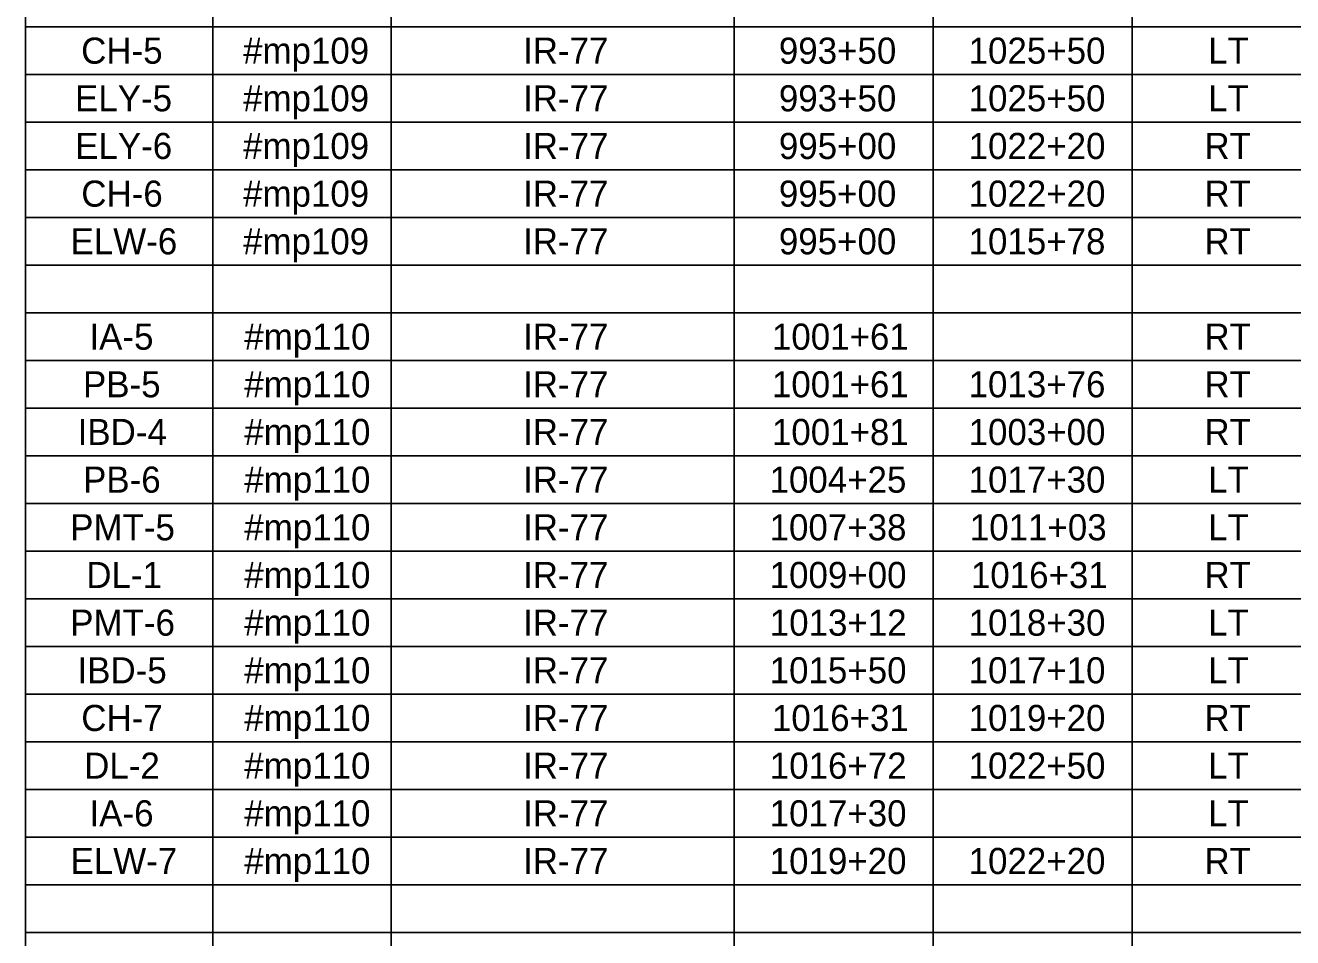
# Model space of a CAD drawing. Extents: x 91011267 to 91022583, y 37007614 to 37014266.
# Drawn here: x 91011277.4 to 91011642.6, y 37010698.6 to 37010961.6 of the extents above; entities that cross this region are included whole.
import ezdxf

# ---------------------------------------------------------------- set-up
doc = ezdxf.new("R2010")
doc.units = 0
doc.layers.add('SC_Scratch2', color=7, linetype='Continuous')
doc.layers.add('SH_Data', color=7, linetype='Continuous')

msp = doc.modelspace()

# ---------------------------------------------------------------- linework, layer by layer
at = {"layer": 'SC_Scratch2'}
msp.add_lwpolyline([(91011277.35, 37011225.45), (91012802.35, 37011225.45), (91012802.35, 37010175.45), (91011277.35, 37010175.45)], close=True, dxfattribs=at)
at = {"layer": 'SH_Data'}
for p, q in [((91011277.35, 37011043.58), (91011277.35, 37010933.68)), ((91011331.39, 37011043.58), (91011331.39, 37010933.68)), ((91011382.8, 37011043.58), (91011382.8, 37010933.68)), ((91011481.65, 37011043.58), (91011481.65, 37010933.68)), ((91011538.99, 37011043.58), (91011538.99, 37010933.68)), ((91011596.32, 37011043.58), (91011596.32, 37010933.68)), ((91011277.35, 37010961.15), (91011596.32, 37010961.15)), ((91011596.32, 37010961.15), (91011650.36, 37010961.15)), ((91011277.35, 37010947.42), (91011596.32, 37010947.42)), ((91011596.32, 37010947.42), (91011650.36, 37010947.42)), ((91011277.35, 37010933.68), (91011596.32, 37010933.68)), ((91011277.35, 37010933.68), (91011277.35, 37010919.94)), ((91011331.39, 37010933.68), (91011331.39, 37010919.94)), ((91011382.8, 37010933.68), (91011382.8, 37010919.94)), ((91011481.65, 37010933.68), (91011481.65, 37010919.94)), ((91011538.99, 37010933.68), (91011538.99, 37010919.94)), ((91011596.32, 37010933.68), (91011650.36, 37010933.68)), ((91011596.32, 37010933.68), (91011596.32, 37010919.94)), ((91011277.35, 37010919.94), (91011596.32, 37010919.94)), ((91011277.35, 37010919.94), (91011277.35, 37010892.46)), ((91011331.39, 37010919.94), (91011331.39, 37010892.46)), ((91011382.8, 37010919.94), (91011382.8, 37010892.46)), ((91011481.65, 37010919.94), (91011481.65, 37010892.46)), ((91011538.99, 37010919.94), (91011538.99, 37010892.46)), ((91011596.32, 37010919.94), (91011650.36, 37010919.94)), ((91011596.32, 37010919.94), (91011596.32, 37010892.46)), ((91011277.35, 37010906.2), (91011596.32, 37010906.2)), ((91011596.32, 37010906.2), (91011650.36, 37010906.2)), ((91011277.35, 37010892.46), (91011596.32, 37010892.46)), ((91011277.35, 37010892.46), (91011277.35, 37010878.72)), ((91011331.39, 37010892.46), (91011331.39, 37010878.72)), ((91011382.8, 37010892.46), (91011382.8, 37010878.72)), ((91011481.65, 37010892.46), (91011481.65, 37010878.72)), ((91011538.99, 37010892.46), (91011538.99, 37010878.72)), ((91011596.32, 37010892.46), (91011650.36, 37010892.46)), ((91011596.32, 37010892.46), (91011596.32, 37010878.72)), ((91011277.35, 37010878.72), (91011596.32, 37010878.72)), ((91011277.35, 37010878.72), (91011277.35, 37010864.99)), ((91011331.39, 37010878.72), (91011331.39, 37010864.99)), ((91011382.8, 37010878.72), (91011382.8, 37010864.99)), ((91011481.65, 37010878.72), (91011481.65, 37010864.99)), ((91011538.99, 37010878.72), (91011538.99, 37010864.99)), ((91011596.32, 37010878.72), (91011650.36, 37010878.72)), ((91011596.32, 37010878.72), (91011596.32, 37010864.99)), ((91011277.35, 37010864.99), (91011596.32, 37010864.99)), ((91011277.35, 37010864.99), (91011277.35, 37010851.25)), ((91011331.39, 37010864.99), (91011331.39, 37010851.25)), ((91011382.8, 37010864.99), (91011382.8, 37010851.25)), ((91011481.65, 37010864.99), (91011481.65, 37010851.25)), ((91011538.99, 37010864.99), (91011538.99, 37010851.25)), ((91011596.32, 37010864.99), (91011650.36, 37010864.99)), ((91011596.32, 37010864.99), (91011596.32, 37010851.25)), ((91011277.35, 37010851.25), (91011596.32, 37010851.25)), ((91011277.35, 37010851.25), (91011277.35, 37010645.17)), ((91011331.39, 37010851.25), (91011331.39, 37010645.17)), ((91011382.8, 37010851.25), (91011382.8, 37010645.17)), ((91011481.65, 37010851.25), (91011481.65, 37010645.17)), ((91011538.99, 37010851.25), (91011538.99, 37010645.17)), ((91011596.32, 37010851.25), (91011650.36, 37010851.25)), ((91011596.32, 37010851.25), (91011596.32, 37010645.17)), ((91011277.35, 37010837.51), (91011596.32, 37010837.51)), ((91011596.32, 37010837.51), (91011650.36, 37010837.51)), ((91011277.35, 37010823.77), (91011596.32, 37010823.77)), ((91011596.32, 37010823.77), (91011650.36, 37010823.77)), ((91011277.35, 37010810.03), (91011596.32, 37010810.03)), ((91011596.32, 37010810.03), (91011650.36, 37010810.03)), ((91011277.35, 37010796.29), (91011596.32, 37010796.29)), ((91011596.32, 37010796.29), (91011650.36, 37010796.29)), ((91011277.35, 37010782.56), (91011596.32, 37010782.56)), ((91011596.32, 37010782.56), (91011650.36, 37010782.56)), ((91011277.35, 37010768.82), (91011596.32, 37010768.82)), ((91011596.32, 37010768.82), (91011650.36, 37010768.82)), ((91011277.35, 37010755.08), (91011596.32, 37010755.08)), ((91011596.32, 37010755.08), (91011650.36, 37010755.08)), ((91011277.35, 37010741.34), (91011596.32, 37010741.34)), ((91011596.32, 37010741.34), (91011650.36, 37010741.34)), ((91011277.35, 37010727.6), (91011596.32, 37010727.6)), ((91011596.32, 37010727.6), (91011650.36, 37010727.6)), ((91011277.35, 37010713.86), (91011596.32, 37010713.86)), ((91011596.32, 37010713.86), (91011650.36, 37010713.86)), ((91011277.35, 37010700.13), (91011596.32, 37010700.13)), ((91011596.32, 37010700.13), (91011650.36, 37010700.13))]:
    msp.add_line(p, q, dxfattribs=at)

# ---------------------------------------------------------------- texts
for s, p in [('CH-5', (91011293.44, 37010950.52)), ('#mp109', (91011340.09, 37010950.52)), ('IR-77', (91011420.79, 37010950.52)), ('993+50', (91011494.52, 37010950.52)), ('1025+50', (91011549.21, 37010950.52)), ('LT', (91011618.23, 37010950.52)), ('#mp109', (91011340.09, 37010936.79)), ('993+50', (91011494.52, 37010936.79)), ('1025+50', (91011549.21, 37010936.79)), ('ELY-5', (91011291.67, 37010936.79)), ('IR-77', (91011420.79, 37010936.79)), ('LT', (91011618.23, 37010936.79)), ('ELY-6', (91011291.7, 37010923.05)), ('#mp109', (91011340.09, 37010923.05)), ('IR-77', (91011420.79, 37010923.05)), ('995+00', (91011494.52, 37010923.05)), ('1022+20', (91011549.21, 37010923.05)), ('RT', (91011617.17, 37010923.05)), ('CH-6', (91011293.47, 37010909.31)), ('#mp109', (91011340.09, 37010909.31)), ('IR-77', (91011420.79, 37010909.31)), ('995+00', (91011494.52, 37010909.31)), ('1022+20', (91011549.21, 37010909.31)), ('RT', (91011617.17, 37010909.31)), ('ELW-6', (91011290.38, 37010895.57)), ('#mp109', (91011340.09, 37010895.57)), ('IR-77', (91011420.79, 37010895.57)), ('995+00', (91011494.52, 37010895.57)), ('1015+78', (91011549.19, 37010895.57)), ('RT', (91011617.17, 37010895.57)), ('IA-5', (91011295.82, 37010868.09)), ('#mp110', (91011340.46, 37010868.09)), ('IR-77', (91011420.79, 37010868.09)), ('1001+61', (91011492.52, 37010868.09)), ('RT', (91011617.17, 37010868.09)), ('PB-5', (91011293.97, 37010854.36)), ('#mp110', (91011340.46, 37010854.36)), ('IR-77', (91011420.79, 37010854.36)), ('1001+61', (91011492.52, 37010854.36)), ('1013+76', (91011549.2, 37010854.36)), ('RT', (91011617.17, 37010854.36)), ('IBD-4', (91011292.42, 37010840.62)), ('#mp110', (91011340.46, 37010840.62)), ('IR-77', (91011420.79, 37010840.62)), ('1001+81', (91011492.52, 37010840.62)), ('1003+00', (91011549.21, 37010840.62)), ('RT', (91011617.17, 37010840.62)), ('PB-6', (91011293.99, 37010826.88)), ('#mp110', (91011340.46, 37010826.88)), ('IR-77', (91011420.79, 37010826.88)), ('1004+25', (91011491.83, 37010826.88)), ('1017+30', (91011549.21, 37010826.88)), ('LT', (91011618.23, 37010826.88)), ('PMT-5', (91011290.27, 37010813.14)), ('#mp110', (91011340.46, 37010813.14)), ('IR-77', (91011420.79, 37010813.14)), ('1007+38', (91011491.85, 37010813.14)), ('1011+03', (91011549.55, 37010813.14)), ('LT', (91011618.23, 37010813.14)), ('DL-1', (91011294.92, 37010799.4)), ('#mp110', (91011340.46, 37010799.4)), ('IR-77', (91011420.79, 37010799.4)), ('1009+00', (91011491.87, 37010799.4)), ('1016+31', (91011549.86, 37010799.4)), ('RT', (91011617.17, 37010799.4)), ('PMT-6', (91011290.29, 37010785.66)), ('#mp110', (91011340.46, 37010785.66)), ('IR-77', (91011420.79, 37010785.66)), ('1013+12', (91011491.9, 37010785.66)), ('1018+30', (91011549.21, 37010785.66)), ('LT', (91011618.23, 37010785.66)), ('IBD-5', (91011292.38, 37010771.93)), ('#mp110', (91011340.46, 37010771.93)), ('IR-77', (91011420.79, 37010771.93)), ('1015+50', (91011491.87, 37010771.93)), ('1017+10', (91011549.21, 37010771.93)), ('LT', (91011618.23, 37010771.93)), ('CH-7', (91011293.47, 37010758.19)), ('#mp110', (91011340.46, 37010758.19)), ('IR-77', (91011420.79, 37010758.19)), ('1016+31', (91011492.52, 37010758.19)), ('1019+20', (91011549.21, 37010758.19)), ('RT', (91011617.17, 37010758.19)), ('DL-2', (91011294.3, 37010744.45)), ('#mp110', (91011340.46, 37010744.45)), ('IR-77', (91011420.79, 37010744.45)), ('1016+72', (91011491.9, 37010744.45)), ('1022+50', (91011549.21, 37010744.45)), ('LT', (91011618.23, 37010744.45)), ('IA-6', (91011295.85, 37010730.71)), ('#mp110', (91011340.46, 37010730.71)), ('IR-77', (91011420.79, 37010730.71)), ('1017+30', (91011491.87, 37010730.71)), ('LT', (91011618.23, 37010730.71)), ('ELW-7', (91011290.38, 37010716.97)), ('#mp110', (91011340.46, 37010716.97)), ('IR-77', (91011420.79, 37010716.97)), ('1019+20', (91011491.87, 37010716.97)), ('1022+20', (91011549.21, 37010716.97)), ('RT', (91011617.17, 37010716.97))]:
    msp.add_text(s, height=7.523, dxfattribs=at).set_placement(p)

doc.saveas('drawing.dxf')
